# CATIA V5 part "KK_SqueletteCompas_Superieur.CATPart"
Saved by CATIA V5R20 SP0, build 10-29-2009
Part number: Squelette_compas_superieur
Bounding box of the stored display mesh (mm): x -200 to 200, y 1344 to 1632, z -2592 to -2100
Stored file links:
  G:\Khaled_CFAO_2011\ST2M\ST2M_GR2\aboulegue\Khaled\CAD_thinkMOTION\KK_SqueletteCompas_Superieur.CATPart
  G:\Khaled_CFAO_2011\ST2M\ST2M_GR2\aboulegue\Khaled\CAD_thinkMOTION\KK_Train_Atterrissage.CATProduct
  G:\Khaled_CFAO_2011\ST2M\ST2M_GR2\aboulegue\Khaled\CAD_thinkMOTION\KK_SqueletteCompas_Inferieur.CATPart
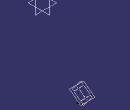
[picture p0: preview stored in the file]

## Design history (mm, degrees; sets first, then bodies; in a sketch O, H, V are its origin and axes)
Set1
  Point1: linked copy from another document
  Point2: linked copy from another document
  Plane1 "Plan reference": linked copy from another document
  Line1: linked copy from another document
Set2 "Set squelette compas superieur"
  Line2: type PtPt, FirstPoint Point1, SecondPoint Point2
  Line3: type Normal, RefPoint Point2, RefSkin Plane1, Start -200, End 200
  Line4: type Normal, RefPoint Point1, RefSkin Plane1, Start -200, End 200
  Plane2 "Plan compas superieur": type 2Lines, Element1 Line2, Element2 Line1
  Plane3 "Plan compas superieur 2": type 2Lines, Element1 Line2, Element2 Line3
Body1 (main body)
